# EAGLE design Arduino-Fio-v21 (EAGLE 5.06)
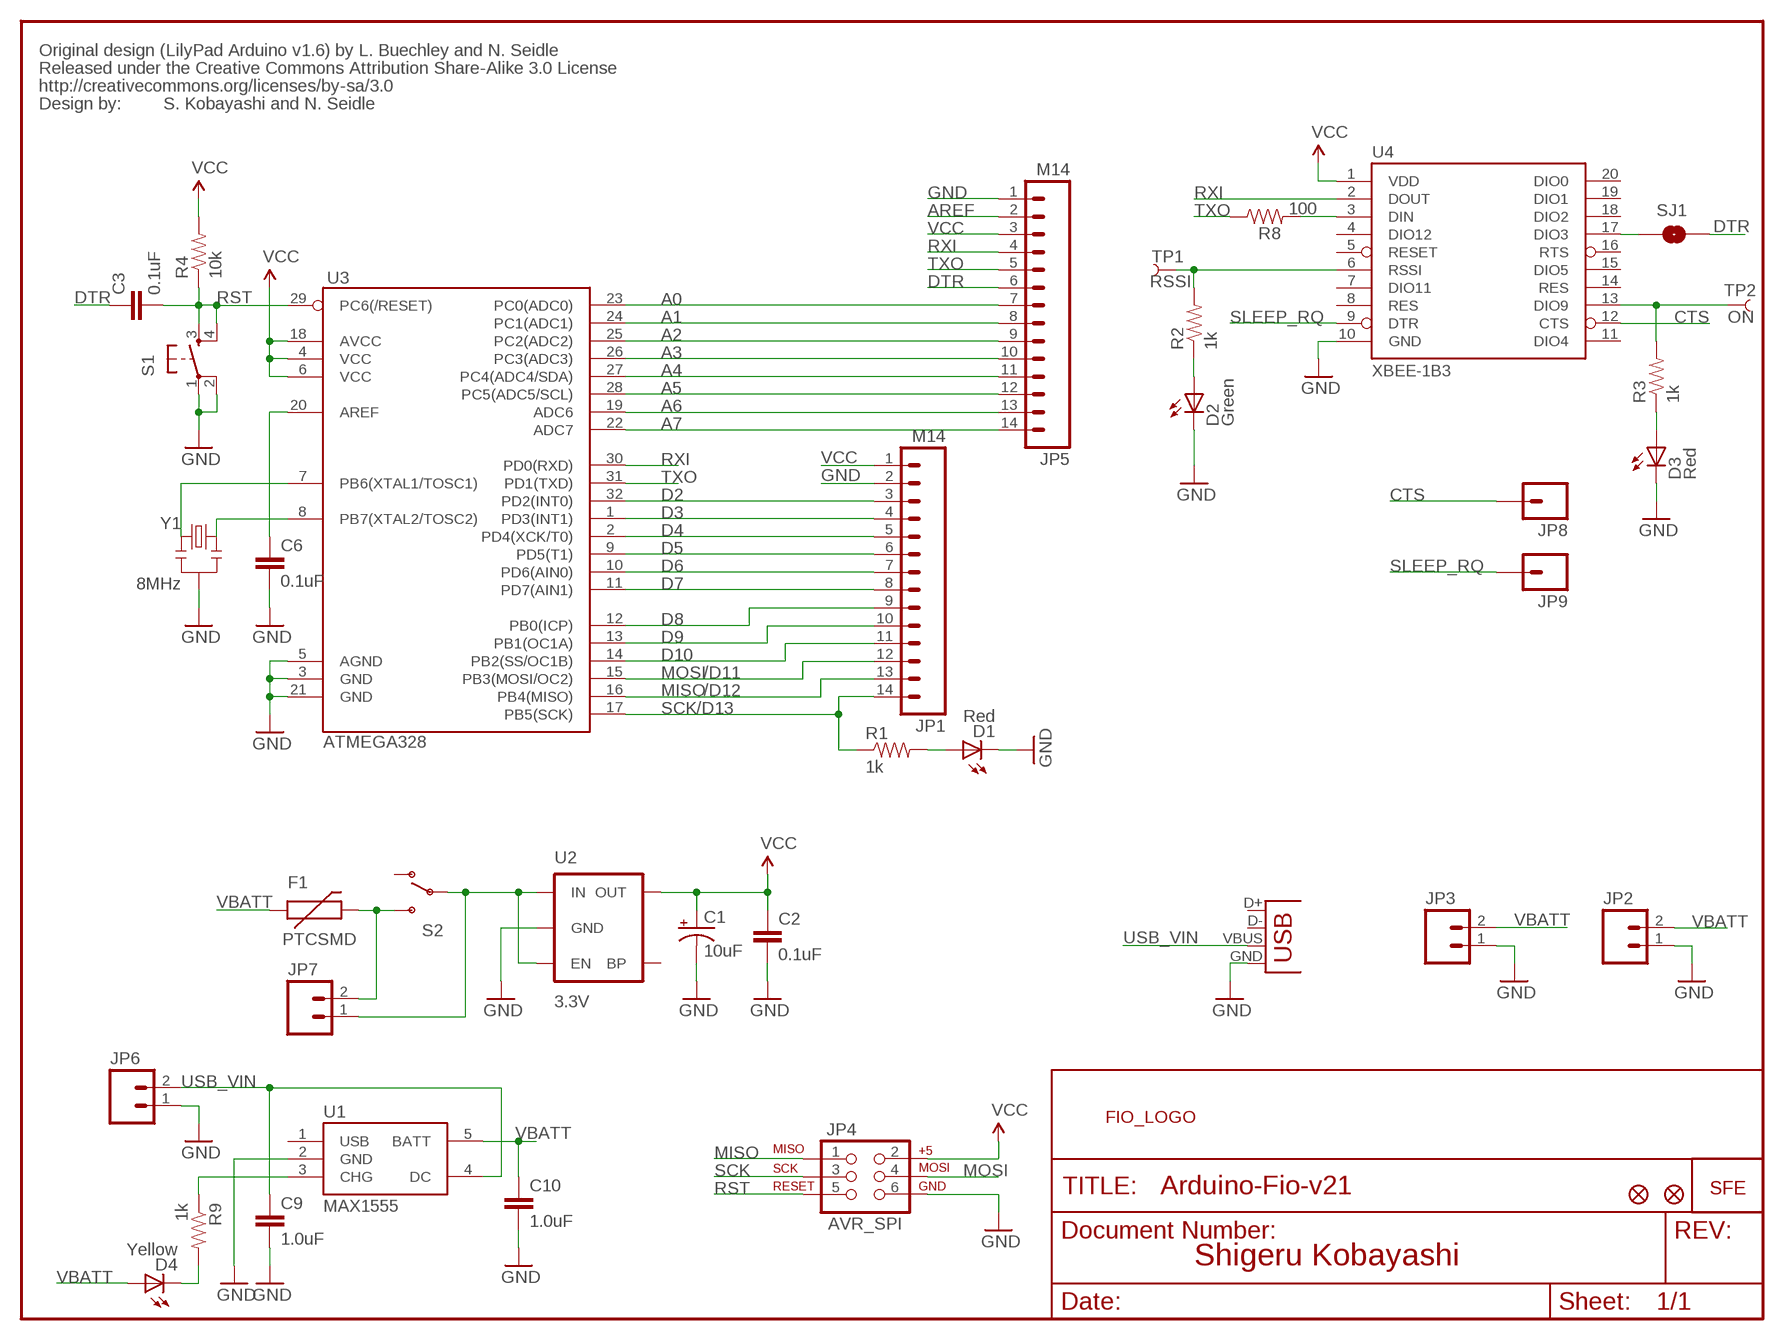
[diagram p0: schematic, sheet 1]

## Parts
C1  10uF  CAP_POL1206  [EIA3216]
C2  0.1uF  CAP0402-CAP  [0402-CAP]
C3  0.1uF  CAP0402-CAP  [0402-CAP]
C6  0.1uF  CAP0402-CAP  [0402-CAP]
C9  1.0uF  CAP0402-CAP  [0402-CAP]
C10  1.0uF  CAP0402-CAP  [0402-CAP]
D1  Red  LED0603  [LED-0603]
D2  Green  LED0603  [LED-0603]
D3  Red  LED0603  [LED-0603]
D4  Yellow  LED0603  [LED-0603]
F1  PTCSMD  [PTC-1206]
JP1  M14  [1X14]
JP2  M02PTH  [1X02]
JP3  M02-JST-2MM-SMT  [S2B-PH]
JP4  AVR_SPI  AVR_SPI_PRG_6PTH  [2X3]
JP5  M14  [1X14]
JP6  M02PTH  [1X02]
JP7  M02PTH  [1X02]
JP8  M01PTH  [1X01]
JP9  M01PTH  [1X01]
R1  1k  RESISTOR0402-RES  [0402-RES]
R2  1k  RESISTOR0402-RES  [0402-RES]
R3  1k  RESISTOR0402-RES  [0402-RES]
R4  10k  RESISTOR0402-RES  [0402-RES]
R8  100  RESISTOR0402-RES  [0402-RES]
R9  1k  RESISTOR0402-RES  [0402-RES]
S1  TAC_SWITCHSMD  [TACTILE_SWITCH_SMD]
S2  SWITCH-SPSTSMD  [AYZ0202]
SJ1  SOLDERJUMPERNC  [SJ_2S]
TP1  RSSI  TEST-POINT3X5  [PAD.03X.05]
TP2  ON  TEST-POINT3X5  [PAD.03X.05]
U1  MAX1555  [SOT23-5]
U2  3.3V  V_REG_LDOSMD  [SOT23-5]
U3  ATMEGA328  ATMEGA168  [TQFP32-08]
U4  XBEE-1B3  [XBEE-SMD]
U$1  LOGO-SFENEW  [SFE-NEW-WEBLOGO]
U$3  CREATIVE_COMMONS  [CREATIVE_COMMONS]
U$4  FIDUCIAL1X2  [FIDUCIAL-1X2]
U$5  FIDUCIAL1X2  [FIDUCIAL-1X2]
U$6  FIO_LOGOV2  [FUNNEL_LOGO_BOTTOM_V2]
X1  USBSMD  [USB-MINIB]
Y1  8MHz  RESONATORSMD  [RESONATOR-SMD]

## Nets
A0: JP5.7 U3.23(PC0(ADC0))
A1: JP5.8 U3.24(PC1(ADC1))
A2: JP5.9 U3.25(PC2(ADC2))
A3: JP5.10 U3.26(PC3(ADC3))
A4: JP5.11 U3.27(PC4(ADC4/SDA))
A5: JP5.12 U3.28(PC5(ADC5/SCL))
A6: JP5.13 U3.19(ADC6)
A7: JP5.14 U3.22(ADC7)
AREF: C6.1 JP5.2 U3.20(AREF)
CTS: JP8.1 U4.12(CTS)
D2: JP1.3 U3.32(PD2(INT0))
D3: JP1.4 U3.1(PD3(INT1))
D4: JP1.5 U3.2(PD4(XCK/T0))
D5: JP1.6 U3.9(PD5(T1))
D6: JP1.7 U3.10(PD6(AIN0))
D7: JP1.8 U3.11(PD7(AIN1))
D8: JP1.9 U3.12(PB0(ICP))
D9: JP1.10 U3.13(PB1(OC1A))
D10: JP1.11 U3.14(PB2(SS/OC1B))
DTR: C3.1 JP5.6 SJ1.2
GND: C1.C(-) C2.2 C6.2 C9.2 C10.2 D1.C D2.C D3.C JP1.2 JP2.1 JP3.1 JP4.6 JP5.1 JP6.1 S1.1 S1.2 U1.2(GND) U2.2(GND) U3.3(GND) U3.5(AGND) U3.21(GND) U4.10(GND) X1.GND Y1.2
MISO: JP1.13 JP4.1 U3.16(PB4(MISO))
MOSI: JP1.12 JP4.4 U3.15(PB3(MOSI/OC2))
N$1: R3.2 TP2.P$1 U4.13(DIO9)
N$2: D1.A R1.2
N$3: D2.A R2.1
N$4: R2.2 TP1.P$1 U4.6(RSSI)
N$5: JP7.1 S2.2(P) U2.1(IN) U2.3(EN)
N$6: D3.A R3.1
N$7: R8.2 U4.3(DIN)
N$8: D4.C R9.2
N$9: F1.2 JP7.2 S2.3(S)
N$10: U3.7(PB6(XTAL1/TOSC1)) Y1.3
N$11: R9.1 U1.3(CHG)
N$12: U3.8(PB7(XTAL2/TOSC2)) Y1.1
N$13: SJ1.1 U4.17(DIO3)
RST: C3.2 JP4.5 R4.1 S1.3 S1.4 U3.29(PC6(/RESET))
RXI: JP5.4 U3.30(PD0(RXD)) U4.2(DOUT)
SCK: JP1.14 JP4.3 R1.1 U3.17(PB5(SCK))
SLEEP_RQ: JP9.1 U4.9(DTR)
TXO: JP5.5 R8.1 U3.31(PD1(TXD))
USB_VIN: C9.1 JP6.2 U1.4(DC) X1.VBUS
VBATT: C10.1 D4.A F1.1 JP2.2 JP3.2 U1.5(BATT)
VCC [VCC]: C1.A(+) C2.1 JP1.1 JP4.2 JP5.3 R4.2 U2.5(OUT) U3.4(VCC) U3.6(VCC) U3.18(AVCC) U4.1(VDD)
Unconnected: S2.1(O) U1.1(USB) U2.4(BP) U4.4(DIO12) U4.5(RESET) U4.7(DIO11) U4.8(RES) U4.11(DIO4) U4.14(RES) U4.15(DIO5) U4.16(RTS) U4.18(DIO2) U4.19(DIO1) U4.20(DIO0) X1.D+ X1.D-

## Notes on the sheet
- Original design (LilyPad Arduino v1.6) by L. Buechley and N. Seidle
- S. Kobayashi and N. Seidle
- /D11
- /D12
- /D13
- Shigeru Kobayashi

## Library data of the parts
C1 = SparkFun:CAP_POL: Capacitor Polarized
C2 C3 C6 C9 C10 = SparkFun:CAP: Capacitor
D1-D4 = SparkFun:LED: LEDs
F1 = SparkFun:PTC: Resettable Fuse PTC
JP1 JP5 = SparkFun:M14: Header 14 Standard 14-pin 0.1" header. Use with straight break away headers (SKU : PRT-00116), right angle break away headers (PRT-00553), swiss pins (PRT-00743), machine pins (PRT-00117), and female headers (PRT-00115).
JP2 JP3 JP6 JP7 = SparkFun:M02: Header 2
JP4 = SparkFun:AVR_SPI_PRG_6: AVR ISP 6 Pin This is the reduced ISP connector for AVR programming. Common on Arduino. This footprint will take up less PCB space and can be used with a 10-pin to 6-pin adapter such as SKU: BOB-08508
JP8 JP9 = SparkFun:M01: Header 1
R1-R4 R8 R9 = SparkFun:RESISTOR: Resistor
S1 = SparkFun:TAC_SWITCH: Momentary Switch Button commonly used for reset or general input. Spark Fun Electronics SKU : COM-00097
S2 = SparkFun:SWITCH-SPST: SPST Switch Simple slide switch. Spark Fun Electronics SKU : COM-00102
SJ1 = SparkFun:SOLDERJUMPER: Solder Jumper
TP1 TP2 = SparkFun:TEST-POINT
U1 = SparkFun:MAX1555: MAX1555 Lithium Charger IC SOT-23 Lithium Polymer charging IC. Schematic element and footprint proven. Spark Fun Electronics SKU : COM-00674
U2 = SparkFun:V_REG_LDO: Voltage Regulator LDO Standard 150mA LDO voltage regulator in SOT-23 layout. Micrel part MIC5205. BP (by-pass) pin is used to lower output noise with 470pF cap.
U3 = SparkFun:ATMEGA168
U4 = SparkFun:XBEE-1
U$1 = SparkFun:LOGO-SFE: Spark Fun Electronics PCB Logo
U$3 = SparkFun:CREATIVE_COMMONS
U$4 U$5 = SparkFun:FIDUCIAL: Fiducial Alignment Points
U$6 = SparkFun:FIO_LOGO
X1 = SparkFun:USB: USB Connectors USB-B-PTH is fully proven SKU : PRT-00139 USB-miniB is fully proven SKU : PRT-00587 USB-A-PCB is untested. USB-A-H is throughly reviewed, but untested. Spark Fun Electronics SKU : PRT-00437 USB-B-SMT is throughly reviewed, but untested. Needs silkscreen touching up. USB-A-S has not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
Y1 = SparkFun:RESONATOR: Resonator Small SMD resonator. This is the itty bitty 10/20MHz resonators with built in caps. CSTCE10M0G55 and CSTCE20M0V53. Footprint has been reviewed closely but hasn't been tested yet.

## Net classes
0 Default: width 0.203 mm
1 VCC: width 0.381 mm
2 LEDPower: width 0.203 mm
3 ButtonSignal: width 0.203 mm

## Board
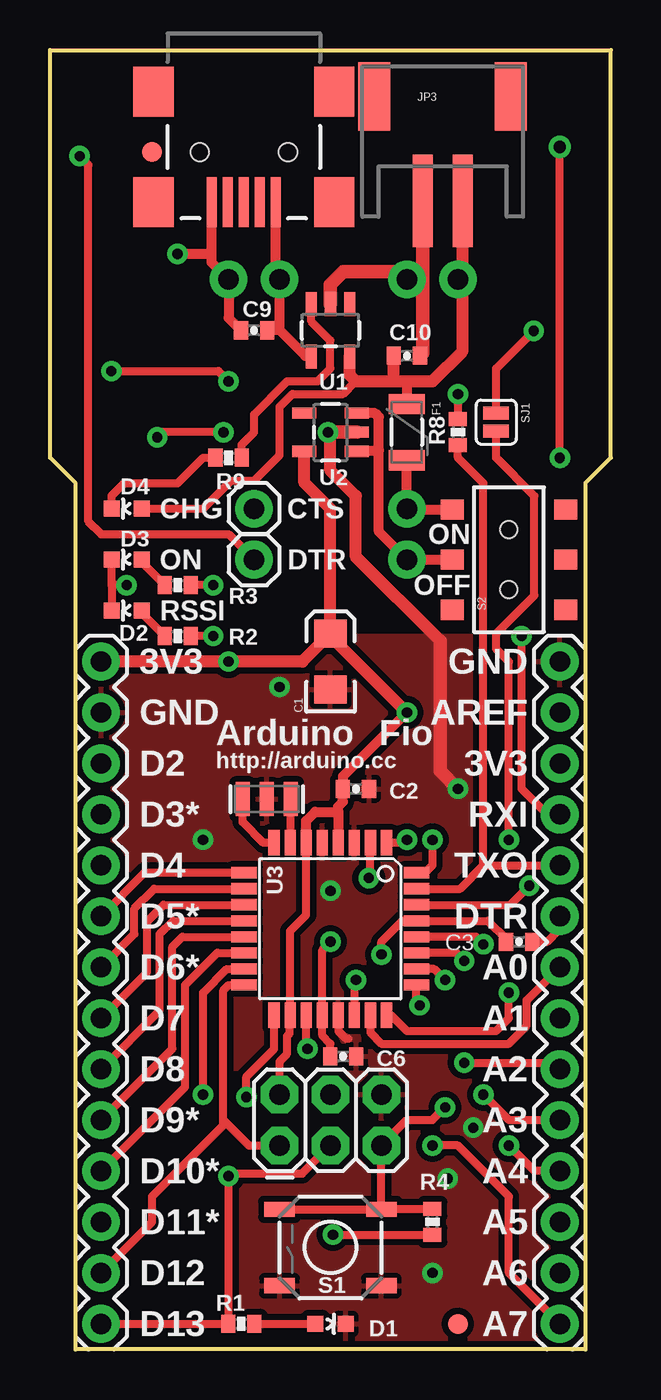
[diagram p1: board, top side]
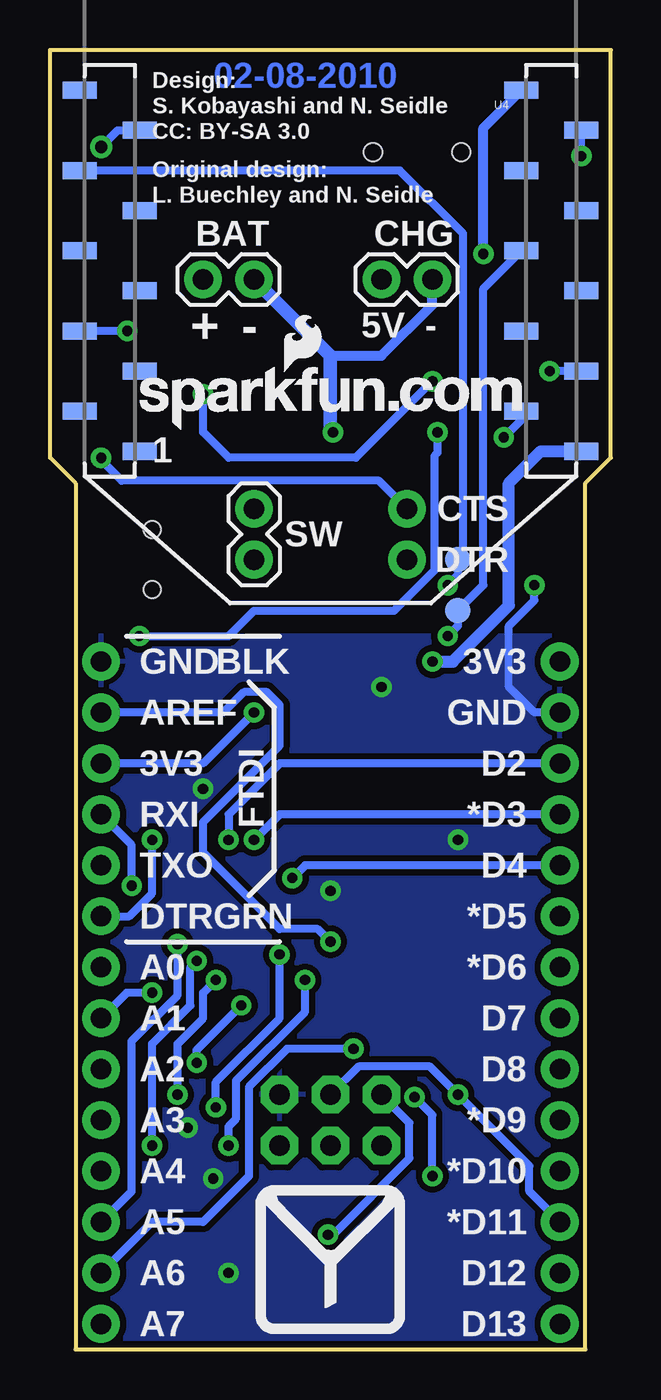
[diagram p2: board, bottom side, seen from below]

Size 27.94 x 64.77 mm. Coordinates in mm from the lower left corner, seen from the top.
Outline: 26.67,43.18 26.67,0 1.27,0 1.27,43.18 0,44.45 0,64.77 27.94,64.77 27.94,44.45 26.67,43.18
Copper layers (1*16): Top 0.035mm / dielectric 1.5mm / Bottom 0.035mm
Design rules "SparkFun *": minimum track width 8mil, minimum drill 20mil, track to track 8mil, track to pad 8mil, pad to pad 8mil, via to via 8mil, smd to smd 8mil, copper to edge 10mil, drill to drill 8mil, minimum pad ring 12mil, minimum via ring 10mil, stop-mask expansion 4mil, vias tented up to drill 25mil, thermal gap 10mil

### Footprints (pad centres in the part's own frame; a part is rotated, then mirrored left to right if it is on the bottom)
EIA3216 = smd 1.4 x 1.6: A 1.4,0; C -1.4,0
0402-CAP = smd 0.7 x 0.9: 1 -0.65,0; 2 0.65,0
LED-0603 = smd 0.8 x 0.8: A 0,-0.75; C 0,0.75
PTC-1206 = smd 1 x 1.8: 1 -1.4,0; 2 1.4,0
1X14 = drill 1.016 pad 1.88 round: 1 0,0; 2 2.54,0; 3 5.08,0; 4 7.62,0; 5 10.16,0; 6 12.7,0; 7 15.24,0; 8 17.78,0; 9 20.32,0; 10 22.86,0; 11 25.4,0; 12 27.94,0; 13 30.48,0; 14 33.02,0
1X02 = drill 1.016 pad 1.88 round: 1 0,0; 2 2.54,0
S2B-PH = smd 1 x 4.6: 1 -1,-3.7; 2 1,-3.7 | smd 1.6 x 3.4: NC1 -3.4,1.5; NC2 3.4,1.5
2X3 = drill 1.016 pad 1.88 octagon: 1 0,0; 2 0,2.54; 3 2.54,0; 4 2.54,2.54; 5 5.08,0; 6 5.08,2.54
1X01 = drill 1.016 pad 1.88 round: 1 0,0
0402-RES = smd 0.7 x 0.9: 1 -0.65,0; 2 0.65,0
TACTILE_SWITCH_SMD = smd 1.524 x 0.762: 1 -2.54,1.905; 2 2.54,1.905; 3 -2.54,-1.905; 4 2.54,-1.905
AYZ0202 = smd 1 x 1.15: 1 -2.5,2.825; 2 0,2.825; 3 2.5,2.825; 4 -2.5,-2.825; 5 0,-2.825; 6 2.5,-2.825 | hole 0.85: 1.5,0; -1.5,0
SJ_2S = smd 0.635 x 1.27: 1 -0.45,0; 2 0.45,0
PAD.03X.05 = smd 1.27 x 1.27: P$1 0,0
SOT23-5 = smd 0.55 x 1.2: 1 -0.95,-1.3; 2 0,-1.3; 3 0.95,-1.3; 4 0.95,1.3; 5 -0.95,1.3
TQFP32-08 = smd 1.27 x 0.559: 1 -4.293,2.8; 2 -4.293,2; 3 -4.293,1.2; 4 -4.293,0.4; 5 -4.293,-0.4; 6 -4.293,-1.2; 7 -4.293,-2; 8 -4.293,-2.8; 17 4.293,-2.8; 18 4.293,-2; 19 4.293,-1.2; 20 4.293,-0.4; 21 4.293,0.4; 22 4.293,1.2; 23 4.293,2; 24 4.293,2.8 | smd 0.559 x 1.27: 9 -2.8,-4.293; 10 -2,-4.293; 11 -1.2,-4.293; 12 -0.4,-4.293; 13 0.4,-4.293; 14 1.2,-4.293; 15 2,-4.293; 16 2.8,-4.293; 25 2.8,4.293; 26 2,4.293; 27 1.2,4.293; 28 0.4,4.293; 29 -0.4,4.293; 30 -1.2,4.293; 31 -2,4.293; 32 -2.8,4.293
XBEE-SMD = smd 1.7 x 0.85: 1 -12.5,20; 2 -9.5,18; 3 -12.5,16; 4 -9.5,14; 5 -12.5,12; 6 -9.5,10; 7 -12.5,8; 8 -9.5,6; 9 -12.5,4; 10 -9.5,2; 11 12.5,2; 12 9.5,4; 13 12.5,6; 14 9.5,8; 15 12.5,10; 16 9.5,12; 17 12.5,14; 18 9.5,16; 19 12.5,18; 20 9.5,20
FIDUCIAL-1X2 = smd 1 x 1: 1 0,0
USB-MINIB = smd 2.5 x 0.5: D+ 2.5,0; D- 2.5,0.8; GND 2.5,-1.6; ID 2.5,-0.8; VBUS 2.5,1.6 | smd 2.5 x 2: GND@1 -3,-4.5; GND@2 -3,4.5; GND@3 2.5,4.5; GND@4 2.5,-4.5 | hole 0.9: 0,2.2; 0,-2.2
RESONATOR-SMD = smd 0.7 x 1.7: 1 -1.2,0; 2 0,0; 3 1.2,0

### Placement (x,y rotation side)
C1  13.97,34.29 90 top
C2  15.24,27.94 0 top
C3  23.37,20.32 180 top
C6  14.61,14.61 0 top
C9  10.16,50.8 180 top
C10  17.78,49.53 0 top
D1  13.97,1.27 270 top
D2  3.81,36.83 90 top
D3  3.81,39.37 90 top
D4  3.81,41.91 90 top
F1  17.78,45.72 270 top
JP1  2.54,34.29 270 top
JP2  17.78,53.34 180 bottom
JP3  19.56,60.96 0 top
JP4  11.43,10.16 0 top
JP5  25.4,34.29 270 top
JP6  8.89,53.34 180 bottom
JP7  17.78,39.37 90 bottom
JP8  10.16,41.91 0 top
JP9  10.16,39.37 0 top
R1  9.53,1.27 0 top
R2  6.35,35.56 0 top
R3  6.35,38.1 0 top
R4  19.05,6.35 270 top
R8  20.32,45.72 90 top
R9  8.89,44.45 180 top
S1  13.97,5.08 180 top
S2  22.86,39.37 90 top
SJ1  22.22,46.23 270 top
TP1  7.62,36.83 0 bottom
TP2  7.62,39.37 0 bottom
U1  13.97,50.8 180 top
U2  13.97,45.72 90 top
U3  13.96,20.96 270 top
U4  13.97,64.77 180 bottom
U$1  23.5,45.85 0 bottom
U$3  not placed on the board
U$4  20.32,1.27 0 top
U$5  5.08,59.69 0 top
U$6  13.97,4.45 0 top
X1  9.65,59.69 270 top
Y1  10.79,27.43 0 top

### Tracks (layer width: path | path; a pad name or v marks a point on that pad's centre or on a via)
A0
  Top 0.406: U3.23 15.96,15.79 16.51,15.24 22.86,15.24 23.75,16.13 23.75,17.4 JP5.7
A1  (via drill 0.51)
  Top 0.406: U3.24 16.98,16.67 17.78,15.88 22.22,15.88 22.86,16.51 v22.86,17.78
  Bottom 0.406: v22.86,17.78 24.13,17.78 JP5.8
A2  (via drill 0.51)
  Top 0.406: U3.25 18.25,17.31 v18.41,17.14 | v20.64,14.29 25.08,14.29 JP5.9
  Bottom 0.406: v18.41,17.14 20.64,14.92 v20.64,14.29
A3  (via drill 0.51)
  Top 0.406: U3.26 19.13,18.96 v19.68,18.41 | v21.59,12.7 22.86,11.43 JP5.10
  Bottom 0.406: v19.68,18.41 20.32,17.78 20.32,16.51 21.59,15.24 v21.59,12.7
A4  (via drill 0.51)
  Top 0.406: U3.27 20.24,19.77 v20.64,19.37 | v22.86,10.16 24.13,8.89 JP5.11
  Bottom 0.406: v22.86,10.16 22.86,15.24 20.95,17.14 20.95,19.05 v20.64,19.37
A5  (via drill 0.51)
  Top 0.406: U3.28 21.22,20.57 v21.59,20.19
  Bottom 0.406: v21.59,20.19 21.59,17.65 23.88,15.37 23.88,7.87 JP5.12
A6  (via drill 0.51)
  Top 0.406: U3.19 12.76,14.99 v12.83,14.99
  Bottom 0.406: JP5.13 22.86,6.35 20.32,6.35 18.03,8.64 18.03,13.08 16.13,14.99 v12.83,14.99
A7  (via drill 0.51)
  Top 0.406: U3.22 15.16,18.34 v15.24,18.41 | v19.05,10.16 20.32,10.16 22.86,7.62 22.86,3.81 JP5.14
  Bottom 0.406: v15.24,18.41 15.24,16.83 18.67,13.4 18.67,11.49 19.05,11.11 v19.05,10.16
AREF  (via drill 0.51)
  Top 0.406: C6.1 13.97,15.24 13.56,15.65 U3.20 13.56,19.91 v13.97,20.32
  Bottom 0.406: v13.97,20.32 14.61,20.95 16.51,20.95 20.32,24.77 20.32,26.29 16.51,30.1 16.51,32.13 17.14,32.77 18.29,32.77 19.3,31.75 JP5.2
CTS  (via drill 0.51, 0.6)
  Top 0.406: v25.4,44.45 v25.4,59.94
  Bottom 0.406: U4.12 24.57,60.77 v25.4,59.94 | JP8.1 11.56,43.31 24.38,43.31 25.4,44.32 v25.4,44.45
D2  (via drill 0.51)
  Top 0.406: U3.32 18.68,23.77 19.05,24.13 v19.05,25.4
  Bottom 0.406: v19.05,25.4 19.05,26.67 16.51,29.21 JP1.3
D3  (via drill 0.51)
  Top 0.406: U3.1 17.64,25.26 v17.78,25.4
  Bottom 0.406: v17.78,25.4 16.51,26.67 JP1.4
D4  (via drill 0.51)
  Top 0.406: U3.2 15.96,23.58 v15.88,23.5
  Bottom 0.406: v15.88,23.5 15.24,24.13 JP1.5
D5
  Top 0.406: U3.9 4.71,23.77 JP1.6
D6
  Top 0.406: U3.10 5.19,22.96 4.19,21.97 4.19,20.7 JP1.7
D7
  Top 0.406: U3.11 5.65,22.16 4.83,21.34 4.83,18.8 JP1.8
D8
  Top 0.406: U3.12 6.12,21.36 5.46,20.7 5.46,16.89 JP1.9
D9
  Top 0.406: U3.13 6.6,20.57 6.1,20.07 6.1,14.99 JP1.10
D10
  Top 0.406: JP1.11 6.73,13.08 6.73,18.16 8.34,19.77 U3.14
DTR  (via drill 0.51)
  Top 0.406: C3.1 24.77,20.32 25.4,20.95 JP5.6 | v22.86,25.4 22.86,34.29 22.22,34.92 22.22,35.69 24.13,37.59 24.13,42.55 22.22,44.45 SJ1.2
  Bottom 0.406: JP5.6 24,21.59 22.86,22.73 v22.86,25.4
GND  (via drill 0.51)
  Top 0.254: JP2.1 18.56,53.34
  Top 0.406: D2.C 3.05,36.83 3.06,36.84 3.06,38.1 | 3.06,38.1 D3.C | 3.06,38.1 3.05,38.1 | v3.81,38.1 3.06,38.1 | U3.21 14.36,15.87 14.73,15.49 14.86,15.49
  Top 0.508: 8.05,54.61 8.05,54.18 JP6.1 8.89,51.42 C9.2 | 8.05,54.61 X1.GND | 8.05,54.61 v6.35,54.61
  Top 0.61: 13.97,45.72 13.97,43.81 15.24,42.55 15.24,39.5 19.43,35.31
  Top 0.66: 18.56,53.72 JP3.1 | U1.2 13.97,53.09 14.61,53.72 18.56,53.72 | 19.43,35.31 19.43,28.83 v20.32,27.94 | 18.56,53.72 18.56,53.34 18.56,49.67 18.41,49.53 C10.2 | v13.84,45.72 13.97,45.72 U2.2
  Bottom 0.406: JP1.2 3.81,31.75 5.08,33.02 5.08,36.07 3.81,37.34 v3.81,38.1 | U4.10 4.54,62.77
  Bottom 0.508: 13.97,49.53 11.43,49.53 8.89,52.07 JP6.1 | v6.35,54.61 6.35,60.89 U4.10
  Bottom 0.66: v13.84,45.72 13.97,45.72 13.97,49.53 JP2.1
  other vias: 11.43,33.02 19.05,3.81 13.97,22.86 7.62,25.4 19.81,8.51 21.08,11.05
  pour Top (isolate 0.305): 1.27,35.56 26.67,35.56 26.67,0 1.27,0
  pour Bottom (isolate 0.305): 1.27,35.56 26.67,35.56 26.67,0 1.27,0
MISO
  Top 0.406: 10.79,10.16 JP4.1 9.91,10.16 8.64,11.43 | JP1.13 5.08,6.35 5.08,7.62 8.64,11.18 8.64,11.43 | U3.16 8.89,18.16 8.64,17.91 8.64,11.43
MOSI  (via drill 0.51)
  Top 0.406: U3.15 8.8,18.96 7.62,17.78 v7.62,12.7
  Bottom 0.406: JP1.12 4.06,7.87 4.06,9.14 v7.62,12.7 9.02,14.1 12.57,14.1 JP4.4
N$1  (via drill 0.51)
  Top 0.406: v8.13,38.1 R3.2
  Bottom 0.406: U4.13 10.51,58.77 7.37,55.63 7.37,39.62 TP2.P$1 7.62,38.61 v8.13,38.1
N$2
  Top 0.406: R1.2 D1.A
N$3
  Top 0.406: D2.A 4.56,36.7 R2.1
N$4  (via drill 0.51)
  Top 0.406: v8.13,35.56 R2.2
  Bottom 0.406: U4.6 6.35,52.89 6.35,38.1 TP1.P$1 7.62,36.07 v8.13,35.56
N$5
  Top 0.508: U2.3 16.2,46.67 16.38,46.48 16.38,44.83 | U2.1 16.32,44.77 16.38,44.83 | 16.38,44.83 16.38,40.77 JP7.1 S2.2
N$6
  Top 0.406: D3.A 4.56,39.24 R3.1
N$7  (via drill 0.51)
  Top 0.406: v8.89,48.26 8.38,48.77 v3.05,48.77 | v20.32,47.62 R8.2
  Bottom 0.406: v8.89,48.26 12.7,44.45 19.05,44.45 20.32,45.72 v20.32,47.62 | U4.3 v3.05,48.77
N$8
  Top 0.406: R9.2 7.62,44.45 6.35,43.18 3.68,43.18 3.06,42.56 D4.C
N$9
  Top 0.508: S2.3 17.82,41.87 JP7.2 F1.2
  Top 0.635: F1.2
N$10
  Top 0.406: U3.7 11.99,25.29 Y1.3
N$11
  Top 0.406: U1.3 13.02,51.24 13.97,50.29 13.97,48.9 13.33,48.26 11.81,48.26 10.16,46.61 10.16,45.72 9.54,45.1 R9.1
N$12
  Top 0.406: Y1.1 9.59,26.28 10.62,25.26 U3.8
N$13  (via drill 0.51)
  Top 0.406: SJ1.1 22.22,48.9 v24.1,50.77
  Bottom 0.406: v24.1,50.77 U4.17
RST  (via drill 0.51)
  Top 0.406: v16.51,19.68 16.51,20.32 17.55,21.36 U3.29 21.82,21.36 22.72,20.46 C3.2 | S1.4 S1.3 | S1.3 JP4.5 17.78,11.43 19.05,11.43 v19.68,12.06 | S1.3 16.64,6.99 16.65,7 R4.1
  Bottom 0.406: v16.51,19.68 16.51,16.51 19.68,13.34 v19.68,12.06
RXI  (via drill 0.51)
  Top 0.406: v23.5,35.56 23.5,27.94 24.77,26.67 JP5.4 | U3.30 22.93,22.16 v23.88,23.11 | v8.64,45.72 5.59,45.72 v5.33,45.47
  Bottom 0.406: v23.5,35.56 19.05,35.56 17.78,36.83 10.79,36.83 8.76,38.86 8.76,44.58 8.64,44.7 v8.64,45.72 | U4.2 4.47,46.33 v5.33,45.47 | JP5.4 23.88,25.15 v23.88,23.11
SCK  (via drill 0.51)
  Top 0.406: U3.17 11.16,14.97 9.78,13.59 v9.78,12.57 | JP1.14 R1.1 v8.89,8.64 9.02,8.76 12.57,8.76 JP4.3 13.72,10.16
  Bottom 0.406: v9.78,12.57 8.89,11.68 v8.89,8.64
SLEEP_RQ  (via drill 0.51)
  Top 0.406: v1.47,59.49 1.91,59.05 1.91,41.27 2.54,40.64 8.89,40.64 JP9.1
  Bottom 0.406: v1.47,59.49 U4.9
TXO
  Top 0.406: U3.31 20.43,22.96 21.59,24.13 | 21.59,24.13 JP5.5 | 21.59,24.13 21.59,43.18 20.32,44.45 R8.1
USB_VIN
  Top 0.508: X1.VBUS 11.25,53.52 JP6.2 11.43,50.8 | 11.43,50.8 12.7,49.53 12.99,49.53 U1.4 | 11.43,50.8 C9.1
VBATT
  Top 0.254: 20.57,53.34 20.56,53.34 JP2.2
  Top 0.406: D4.A 7.62,41.91 9.02,43.31 10.16,43.31 11.43,44.58 11.43,46.99 12.06,47.62 14.61,47.62 15.24,48.26
  Top 0.508: 17.78,48.26 F1.1
  Top 0.61: JP3.2 20.56,53.34 20.56,49.77 19.05,48.26 17.78,48.26 17.14,48.26 | 17.14,48.26 15.24,48.26 14.92,48.58 U1.5 | C10.1 17.13,48.27 17.14,48.26
VCC  (via drill 0.51)
  Top 0.406: U3.6 12.76,21.65 11.96,20.85 U3.18 11.94,16.65 11.94,15.75 11.81,15.62 11.81,14.73 11.43,14.35 JP4.2 | R4.2 14.11,5.7 v14.1,5.71
  Top 0.508: 14.36,26.8 14.36,27.06 | 14.36,26.8 U3.4 | U3.6 12.76,26.35 13.21,26.8 14.36,26.8 | v17.78,31.75 14.61,28.57 14.61,27.94 | 14.36,27.06 14.35,27.05 | C2.1 14.59,27.29 14.36,27.06
  Top 0.61: U2.5 12.67,43.21 13.97,41.91 C1.A | C1.A 13.97,35.56 v17.78,31.75 | C1.A 12.57,34.29 v8.89,34.29 JP1.1
  Top 0.635: C2.1 14.61,27.94
  Bottom 0.406: JP5.3 20.32,29.21 v17.78,31.75 | v14.1,5.71 13.84,5.71 10.03,9.53 10.03,11.3 JP4.2
  Bottom 0.61: U4.1 3.49,44.77 5.08,43.18 5.08,37.08 7.87,34.29 v8.89,34.29

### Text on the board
Bottom: 02-08-2010
tPlace: CHG | CTS | ON | ON | DTR | OFF | RSSI | GND | 3V3 | AREF | GND | Arduino | Fio | 3V3 | D2 | http://arduino.cc | RXI | D3* | TXO | D4 | DTR | D5* | A0 | D6* | A1 | D7 | A2 | D8 | A3 | D9* | A4 | D10* | A5 | D11* | A6 | D12 | A7 | D13 | S. Kobayashi and N. Seidle
bPlace: Design: | S. Kobayashi and N. Seidle | CC: BY-SA 3.0 | Original design: | L. Buechley and N. Seidle | CHG | BAT | - | 5V | - | + | 1 | CTS | DTR | SW | 3V3 | BLK | GND | GND | AREF | D2 | FTDI | 3V3 | *D3 | RXI | D4 | TXO | *D5 | GRN | DTR | *D6 | A0 | D7 | A1 | D8 | A2 | *D9 | A3 | *D10 | A4 | *D11 | A5 | D12 | A6 | D13 | A7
